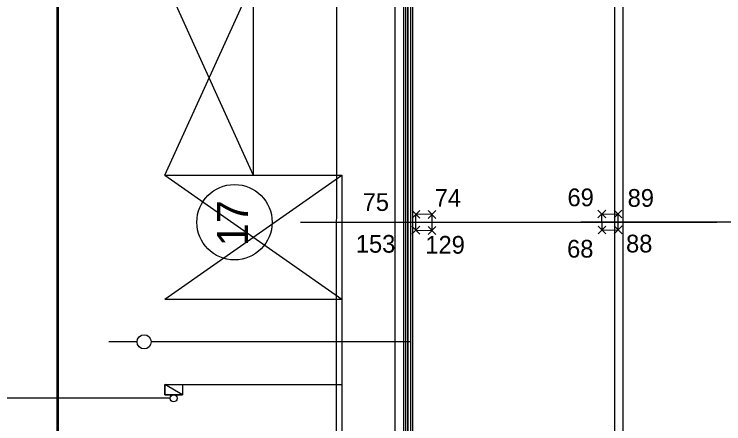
# Model space of a CAD drawing. Extents: x -264205 to -263659, y -1242401 to -1242060.
# Drawn here: x -263925.35 to -263905.31, y -1242194.57 to -1242183.01 of the extents above; entities that cross this region are included whole.
import ezdxf

# ---------------------------------------------------------------- set-up
doc = ezdxf.new("R2010")
doc.units = 0
for name, color, linetype in [('BOD_CISLO', 7, 'Continuous'), ('BOD_SYMBOL', 7, 'Continuous'), ('KFA_SO_10-1_BETONOVE_STLPY', 7, 'Continuous'), ('KFA_SO_10-1_STRECHY', 7, 'Continuous'), ('KFA_SO_10-1_TRIBUNA_A_HLAVNA_BUDOVA', 7, 'Continuous'), ('OBRUBNIKY_KOMUNIKACIE_PROJEKT', 7, 'Continuous'), ('OSI_STAVBY_KFA', 7, 'Continuous'), ('SITUACIA_DSP_2D', 7, 'Continuous'), ('TDZ_VODOROVNE_PROJEKT', 7, 'Continuous')]:
    doc.layers.add(name, color=color, linetype=linetype)

msp = doc.modelspace()

# ---------------------------------------------------------------- linework, layer by layer
at = {"layer": 'BOD_SYMBOL'}
for p, q in [((-263914.112, -1242188.769), (-263913.891, -1242188.549)), ((-263913.891, -1242188.769), (-263914.112, -1242188.549)), ((-263913.658, -1242188.776), (-263913.437, -1242188.556)), ((-263913.437, -1242188.776), (-263913.658, -1242188.556)), ((-263908.862, -1242188.762), (-263908.641, -1242188.541)), ((-263908.641, -1242188.762), (-263908.862, -1242188.541)), ((-263908.405, -1242188.759), (-263908.184, -1242188.539)), ((-263908.184, -1242188.759), (-263908.405, -1242188.539)), ((-263914.116, -1242189.22), (-263913.894, -1242188.998)), ((-263913.894, -1242189.22), (-263914.116, -1242188.998)), ((-263913.658, -1242189.228), (-263913.437, -1242189.007)), ((-263913.437, -1242189.228), (-263913.658, -1242189.007)), ((-263908.857, -1242189.214), (-263908.636, -1242188.992)), ((-263908.636, -1242189.214), (-263908.857, -1242188.992)), ((-263908.402, -1242189.208), (-263908.181, -1242188.988)), ((-263908.181, -1242189.208), (-263908.402, -1242188.988))]:
    msp.add_line(p, q, dxfattribs=at)
at = {"layer": 'KFA_SO_10-1_BETONOVE_STLPY'}
for p, q in [((-263914.005, -1242189.109), (-263914.002, -1242188.659)), ((-263913.547, -1242188.666), (-263914.002, -1242188.659)), ((-263913.547, -1242189.117), (-263913.547, -1242188.666)), ((-263908.752, -1242188.651), (-263908.295, -1242188.649)), ((-263908.747, -1242189.103), (-263908.752, -1242188.651)), ((-263908.291, -1242189.098), (-263908.295, -1242188.649)), ((-263914.005, -1242189.109), (-263913.547, -1242189.117)), ((-263908.747, -1242189.103), (-263908.291, -1242189.098))]:
    msp.add_line(p, q, dxfattribs=at)
at = {"layer": 'KFA_SO_10-1_STRECHY'}
msp.add_line((-263908.157, -1242227.179), (-263908.136, -1242101.59), dxfattribs=at)
at = {"layer": 'KFA_SO_10-1_TRIBUNA_A_HLAVNA_BUDOVA'}
for p, q in [((-263914.23, -1242196.348), (-263914.235, -1242132.417)), ((-263914.23, -1242196.348), (-263914.235, -1242132.417)), ((-263916.245, -1242132.722), (-263916.25, -1242195.816))]:
    msp.add_line(p, q, dxfattribs=at)
at = {"layer": 'OBRUBNIKY_KOMUNIKACIE_PROJEKT'}
msp.add_line((-263914.143, -1242196.333), (-263914.143, -1242132.433), dxfattribs=at)
at = {"layer": 'OSI_STAVBY_KFA'}
for p, q in [((-263908.393, -1242083.237), (-263908.393, -1242246.707)), ((-263917.265, -1242188.882), (-263905.505, -1242188.882)), ((-263917.265, -1242188.882), (-263905.505, -1242188.882)), ((-263792.653, -1242188.882), (-263909.343, -1242188.882))]:
    msp.add_line(p, q, dxfattribs=at)
msp.add_circle((-263919.125, -1242188.882), 1.064, dxfattribs=at)
at = {"layer": 'SITUACIA_DSP_2D'}
for p, q in [((-263924.143, -1242082.64), (-263924.143, -1242185.14)), ((-263914.218, -1242196.332), (-263914.218, -1242132.432)), ((-263914.143, -1242196.333), (-263914.143, -1242132.433)), ((-263914.1, -1242168.521), (-263914.1, -1242199.486)), ((-263914.6, -1242168.728), (-263914.6, -1242199.693)), ((-263914.35, -1242168.625), (-263914.35, -1242199.59)), ((-263914.293, -1242175.482), (-263914.293, -1242210.482)), ((-263924.143, -1242185.14), (-263924.143, -1242250.14)), ((-263921.877, -1242192.257), (-263922.677, -1242192.257)), ((-263915.293, -1242192.257), (-263921.477, -1242192.257)), ((-263914.143, -1242192.257), (-263915.293, -1242192.257)), ((-263921.093, -1242193.752), (-263921.093, -1242193.462)), ((-263921.093, -1242193.462), (-263920.593, -1242193.462)), ((-263920.593, -1242193.752), (-263921.093, -1242193.462)), ((-263920.593, -1242193.752), (-263921.093, -1242193.462)), ((-263921.093, -1242193.462), (-263921.093, -1242193.752)), ((-263920.593, -1242193.462), (-263920.593, -1242193.752)), ((-263920.593, -1242193.752), (-263921.093, -1242193.752)), ((-263921.093, -1242193.752), (-263920.593, -1242193.752)), ((-263920.944, -1242193.852), (-263925.798, -1242193.852))]:
    msp.add_line(p, q, dxfattribs=at)
for centre, radius in [((-263921.677, -1242192.257), 0.2), ((-263920.844, -1242193.852), 0.1)]:
    msp.add_circle(centre, radius, dxfattribs=at)
at = {"layer": 'TDZ_VODOROVNE_PROJEKT'}
for p, q in [((-263924.088, -1242241.458), (-263924.093, -1242087.307)), ((-263918.593, -1242141.207), (-263918.593, -1242187.557)), ((-263921.093, -1242182.062), (-263918.593, -1242187.557)), ((-263921.093, -1242187.557), (-263918.593, -1242182.062)), ((-263921.093, -1242187.557), (-263916.093, -1242187.557)), ((-263921.093, -1242187.557), (-263916.093, -1242191.057)), ((-263921.093, -1242191.057), (-263916.093, -1242187.557)), ((-263916.093, -1242187.557), (-263916.093, -1242241.458)), ((-263921.093, -1242191.057), (-263916.093, -1242191.057)), ((-263921.093, -1242193.457), (-263916.093, -1242193.457))]:
    msp.add_line(p, q, dxfattribs=at)

# ---------------------------------------------------------------- texts
at = {"layer": 'BOD_CISLO'}
for s, p in [('74', (-263913.473, -1242188.447)), ('69', (-263909.723, -1242188.432)), ('89', (-263908.024, -1242188.447)), ('75', (-263915.507, -1242188.564)), ('153', (-263915.699, -1242189.742)), ('129', (-263913.736, -1242189.77)), ('88', (-263908.069, -1242189.735)), ('68', (-263909.734, -1242189.881))]:
    msp.add_text(s, height=0.5, dxfattribs=at).set_placement(p)
at = {"layer": 'OSI_STAVBY_KFA'}
msp.add_text('17', height=0.875, rotation=90, dxfattribs=at).set_placement((-263918.744, -1242189.562))

doc.saveas('drawing.dxf')
